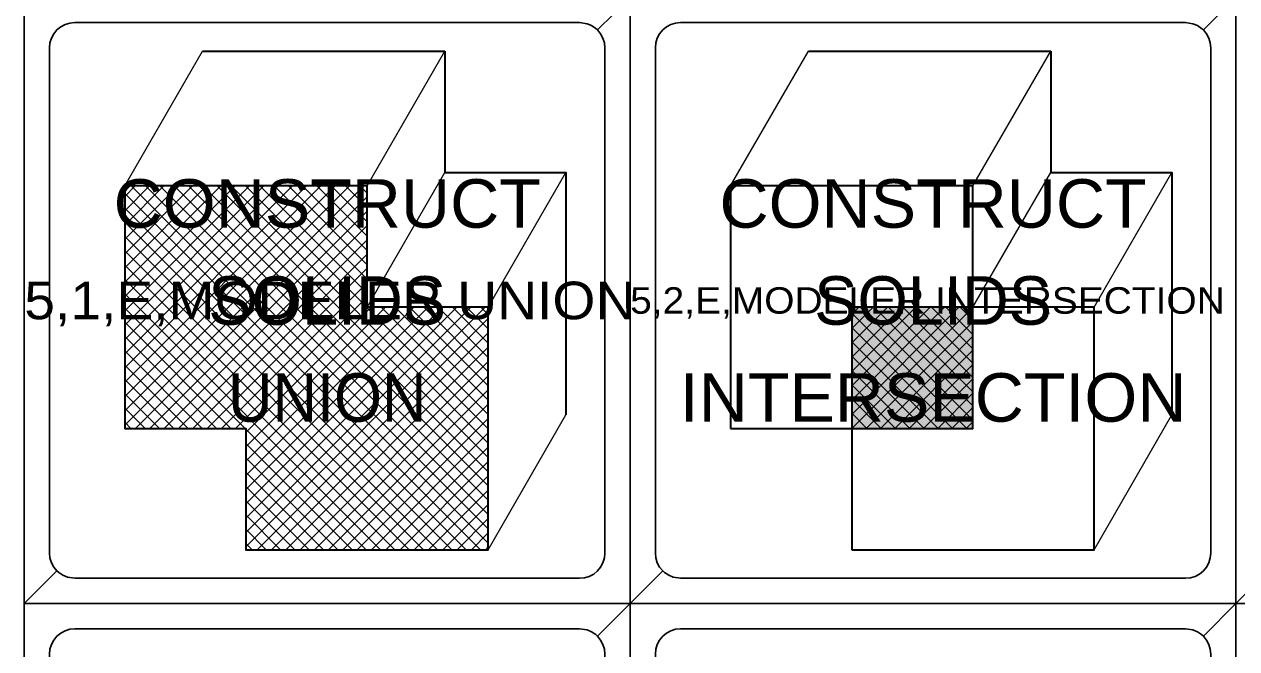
# Model space of a CAD drawing. Extents: x 95909.2 to 95923.3, y 90965 to 90971.2.
# Drawn here: x 95909.787 to 95910.988, y 90968.116 to 90968.734 of the extents above; entities that cross this region are included whole.
import ezdxf
from ezdxf.enums import TextEntityAlignment as Align

# ---------------------------------------------------------------- set-up
doc = ezdxf.new("R2010")
doc.units = 0
doc.header["$LTSCALE"] = 0.019
for name, color, linetype, lineweight in [('1', 7, 'Continuous', 25), ('10', 7, 'Continuous', 13), ('2', 7, 'Continuous', 25), ('3', 7, 'Continuous', 25), ('4', 7, 'Continuous', 25), ('6', 7, 'Continuous', 13)]:
    doc.layers.add(name, color=color, linetype=linetype, lineweight=lineweight)
doc.layers.add('5', color=7, linetype='Continuous')
doc.layers.add('63', color=7, linetype='Continuous')

msp = doc.modelspace()

# ---------------------------------------------------------------- hatches: boundary and pattern name
at = {"layer": '6'}
msp.add_hatch(color=256, dxfattribs=at).paths.add_polyline_path([(95910.6063, 90968.3336), (95910.7263, 90968.3336), (95910.7263, 90968.4536), (95910.6063, 90968.4536)])

# ---------------------------------------------------------------- linework, layer by layer
at = {"layer": '1'}
for points in [[(95909.7868, 90968.1603), (95910.3868, 90968.1603), (95910.3868, 90968.7603), (95909.7868, 90968.7603)], [(95910.3868, 90968.1603), (95910.9868, 90968.1603), (95910.9868, 90968.7603), (95910.3868, 90968.7603)], [(95910.9868, 90968.1603), (95911.5868, 90968.1603), (95911.5868, 90968.7603), (95910.9868, 90968.7603)], [(95909.7868, 90967.5603), (95910.3868, 90967.5603), (95910.3868, 90968.1603), (95909.7868, 90968.1603)], [(95910.3868, 90967.5603), (95910.9868, 90967.5603), (95910.9868, 90968.1603), (95910.3868, 90968.1603)], [(95910.9868, 90967.5603), (95911.5868, 90967.5603), (95911.5868, 90968.1603), (95910.9868, 90968.1603)]]:
    msp.add_lwpolyline(points, close=True, dxfattribs=at)
at = {"layer": '10'}
msp.add_lwpolyline([(95909.7868, 90971.1603), (95915.7868, 90971.1603), (95915.7868, 90966.3603), (95909.7868, 90966.3603)], close=True, dxfattribs=at)
at = {"layer": '2'}
for points in [[(95909.7868, 90968.1603), (95910.3868, 90968.1603), (95910.3868, 90968.7603), (95909.7868, 90968.7603)], [(95910.3868, 90968.1603), (95910.9868, 90968.1603), (95910.9868, 90968.7603), (95910.3868, 90968.7603)], [(95910.9868, 90968.1603), (95911.5868, 90968.1603), (95911.5868, 90968.7603), (95910.9868, 90968.7603)], [(95909.7868, 90967.5603), (95910.3868, 90967.5603), (95910.3868, 90968.1603), (95909.7868, 90968.1603)], [(95910.3868, 90967.5603), (95910.9868, 90967.5603), (95910.9868, 90968.1603), (95910.3868, 90968.1603)], [(95910.9868, 90967.5603), (95911.5868, 90967.5603), (95911.5868, 90968.1603), (95910.9868, 90968.1603)]]:
    msp.add_lwpolyline(points, close=True, dxfattribs=at)
at = {"layer": '3'}
for points in [[(95910.3868, 90968.7603), (95909.7868, 90968.7603), (95909.7868, 90968.1603), (95909.8191, 90968.1926), (95909.816, 90968.1964), (95909.8137, 90968.2007), (95909.8123, 90968.2054), (95909.8118, 90968.2103), (95909.8118, 90968.7103), (95909.8123, 90968.7152), (95909.8137, 90968.7199), (95909.816, 90968.7242), (95909.8191, 90968.728), (95909.8191, 90968.728), (95909.8229, 90968.7311), (95909.8272, 90968.7334), (95909.8319, 90968.7348), (95909.8368, 90968.7353), (95910.3368, 90968.7353), (95910.3441, 90968.7342), (95910.3486, 90968.7323), (95910.3527, 90968.7296), (95910.3545, 90968.728)], [(95910.9868, 90968.7603), (95910.3868, 90968.7603), (95910.3868, 90968.1603), (95910.4191, 90968.1926), (95910.416, 90968.1964), (95910.4137, 90968.2007), (95910.4123, 90968.2054), (95910.4118, 90968.2103), (95910.4118, 90968.7103), (95910.4123, 90968.7152), (95910.4137, 90968.7199), (95910.416, 90968.7242), (95910.4191, 90968.728), (95910.4191, 90968.728), (95910.4229, 90968.7311), (95910.4272, 90968.7334), (95910.4319, 90968.7348), (95910.4368, 90968.7353), (95910.9368, 90968.7353), (95910.9441, 90968.7342), (95910.9486, 90968.7323), (95910.9527, 90968.7296), (95910.9545, 90968.728)], [(95911.5868, 90968.7603), (95910.9868, 90968.7603), (95910.9868, 90968.1603), (95911.0191, 90968.1926), (95911.016, 90968.1964), (95911.0137, 90968.2007), (95911.0123, 90968.2054), (95911.0118, 90968.2103), (95911.0118, 90968.7103), (95911.0123, 90968.7152), (95911.0137, 90968.7199), (95911.016, 90968.7242), (95911.0191, 90968.728), (95911.0191, 90968.728), (95911.0229, 90968.7311), (95911.0272, 90968.7334), (95911.0319, 90968.7348), (95911.0368, 90968.7353), (95911.5368, 90968.7353), (95911.5441, 90968.7342), (95911.5486, 90968.7323), (95911.5527, 90968.7296), (95911.5545, 90968.728)], [(95910.3868, 90968.1603), (95909.7868, 90968.1603), (95909.7868, 90967.5603), (95909.8191, 90967.5926), (95909.816, 90967.5964), (95909.8137, 90967.6007), (95909.8123, 90967.6054), (95909.8118, 90967.6103), (95909.8118, 90968.1103), (95909.8123, 90968.1152), (95909.8137, 90968.1199), (95909.816, 90968.1242), (95909.8191, 90968.128), (95909.8191, 90968.128), (95909.8229, 90968.1311), (95909.8272, 90968.1334), (95909.8319, 90968.1348), (95909.8368, 90968.1353), (95910.3368, 90968.1353), (95910.3441, 90968.1342), (95910.3486, 90968.1323), (95910.3527, 90968.1296), (95910.3545, 90968.128)], [(95910.9868, 90968.1603), (95910.3868, 90968.1603), (95910.3868, 90967.5603), (95910.4191, 90967.5926), (95910.416, 90967.5964), (95910.4137, 90967.6007), (95910.4123, 90967.6054), (95910.4118, 90967.6103), (95910.4118, 90968.1103), (95910.4123, 90968.1152), (95910.4137, 90968.1199), (95910.416, 90968.1242), (95910.4191, 90968.128), (95910.4191, 90968.128), (95910.4229, 90968.1311), (95910.4272, 90968.1334), (95910.4319, 90968.1348), (95910.4368, 90968.1353), (95910.9368, 90968.1353), (95910.9441, 90968.1342), (95910.9486, 90968.1323), (95910.9527, 90968.1296), (95910.9545, 90968.128)], [(95911.5868, 90968.1603), (95910.9868, 90968.1603), (95910.9868, 90967.5603), (95911.0191, 90967.5926), (95911.016, 90967.5964), (95911.0137, 90967.6007), (95911.0123, 90967.6054), (95911.0118, 90967.6103), (95911.0118, 90968.1103), (95911.0123, 90968.1152), (95911.0137, 90968.1199), (95911.016, 90968.1242), (95911.0191, 90968.128), (95911.0191, 90968.128), (95911.0229, 90968.1311), (95911.0272, 90968.1334), (95911.0319, 90968.1348), (95911.0368, 90968.1353), (95911.5368, 90968.1353), (95911.5441, 90968.1342), (95911.5486, 90968.1323), (95911.5527, 90968.1296), (95911.5545, 90968.128)]]:
    msp.add_lwpolyline(points, close=True, dxfattribs=at)
at = {"layer": '4'}
for points in [[(95909.7868, 90968.1603), (95910.3868, 90968.1603), (95910.3868, 90968.7603), (95910.3545, 90968.728), (95910.3576, 90968.7242), (95910.3599, 90968.7199), (95910.3613, 90968.7152), (95910.3618, 90968.7103), (95910.3618, 90968.2103), (95910.3613, 90968.2054), (95910.3599, 90968.2007), (95910.3576, 90968.1964), (95910.3545, 90968.1926), (95910.3545, 90968.1926), (95910.3507, 90968.1895), (95910.3464, 90968.1872), (95910.3417, 90968.1858), (95910.3368, 90968.1853), (95909.8368, 90968.1853), (95909.8295, 90968.1864), (95909.825, 90968.1883), (95909.8209, 90968.191), (95909.8191, 90968.1926)], [(95910.3868, 90968.1603), (95910.9868, 90968.1603), (95910.9868, 90968.7603), (95910.9545, 90968.728), (95910.9576, 90968.7242), (95910.9599, 90968.7199), (95910.9613, 90968.7152), (95910.9618, 90968.7103), (95910.9618, 90968.2103), (95910.9613, 90968.2054), (95910.9599, 90968.2007), (95910.9576, 90968.1964), (95910.9545, 90968.1926), (95910.9545, 90968.1926), (95910.9507, 90968.1895), (95910.9464, 90968.1872), (95910.9417, 90968.1858), (95910.9368, 90968.1853), (95910.4368, 90968.1853), (95910.4295, 90968.1864), (95910.425, 90968.1883), (95910.4209, 90968.191), (95910.4191, 90968.1926)], [(95910.9868, 90968.1603), (95911.5868, 90968.1603), (95911.5868, 90968.7603), (95911.5545, 90968.728), (95911.5576, 90968.7242), (95911.5599, 90968.7199), (95911.5613, 90968.7152), (95911.5618, 90968.7103), (95911.5618, 90968.2103), (95911.5613, 90968.2054), (95911.5599, 90968.2007), (95911.5576, 90968.1964), (95911.5545, 90968.1926), (95911.5545, 90968.1926), (95911.5507, 90968.1895), (95911.5464, 90968.1872), (95911.5417, 90968.1858), (95911.5368, 90968.1853), (95911.0368, 90968.1853), (95911.0295, 90968.1864), (95911.025, 90968.1883), (95911.0209, 90968.191), (95911.0191, 90968.1926)], [(95909.7868, 90967.5603), (95910.3868, 90967.5603), (95910.3868, 90968.1603), (95910.3545, 90968.128), (95910.3576, 90968.1242), (95910.3599, 90968.1199), (95910.3613, 90968.1152), (95910.3618, 90968.1103), (95910.3618, 90967.6103), (95910.3613, 90967.6054), (95910.3599, 90967.6007), (95910.3576, 90967.5964), (95910.3545, 90967.5926), (95910.3545, 90967.5926), (95910.3507, 90967.5895), (95910.3464, 90967.5872), (95910.3417, 90967.5858), (95910.3368, 90967.5853), (95909.8368, 90967.5853), (95909.8295, 90967.5864), (95909.825, 90967.5883), (95909.8209, 90967.591), (95909.8191, 90967.5926)], [(95910.3868, 90967.5603), (95910.9868, 90967.5603), (95910.9868, 90968.1603), (95910.9545, 90968.128), (95910.9576, 90968.1242), (95910.9599, 90968.1199), (95910.9613, 90968.1152), (95910.9618, 90968.1103), (95910.9618, 90967.6103), (95910.9613, 90967.6054), (95910.9599, 90967.6007), (95910.9576, 90967.5964), (95910.9545, 90967.5926), (95910.9545, 90967.5926), (95910.9507, 90967.5895), (95910.9464, 90967.5872), (95910.9417, 90967.5858), (95910.9368, 90967.5853), (95910.4368, 90967.5853), (95910.4295, 90967.5864), (95910.425, 90967.5883), (95910.4209, 90967.591), (95910.4191, 90967.5926)]]:
    msp.add_lwpolyline(points, close=True, dxfattribs=at)
at = {"layer": '6'}
for p, q in [((95909.8863, 90968.5736), (95909.9633, 90968.707)), ((95910.1263, 90968.5736), (95910.2033, 90968.707)), ((95910.4863, 90968.5736), (95910.5633, 90968.707)), ((95910.7263, 90968.5736), (95910.8033, 90968.707)), ((95910.1263, 90968.4536), (95910.2033, 90968.587)), ((95910.2463, 90968.4536), (95910.3233, 90968.587)), ((95910.7263, 90968.4536), (95910.8033, 90968.587)), ((95910.8463, 90968.4536), (95910.9233, 90968.587)), ((95909.8863, 90968.5632), (95909.8967, 90968.5736)), ((95909.8863, 90968.5491), (95909.9108, 90968.5736)), ((95909.8863, 90968.5349), (95909.925, 90968.5736)), ((95909.8863, 90968.5208), (95909.9391, 90968.5736)), ((95909.8863, 90968.5066), (95909.9533, 90968.5736)), ((95909.8863, 90968.4925), (95909.9674, 90968.5736)), ((95909.8863, 90968.4783), (95909.9816, 90968.5736)), ((95909.8863, 90968.4642), (95909.9957, 90968.5736)), ((95909.8863, 90968.4501), (95910.0098, 90968.5736)), ((95909.8863, 90968.4359), (95910.024, 90968.5736)), ((95909.8863, 90968.4218), (95910.0381, 90968.5736)), ((95909.8863, 90968.4076), (95910.0523, 90968.5736)), ((95909.8863, 90968.3935), (95910.0664, 90968.5736)), ((95909.8863, 90968.3794), (95910.0805, 90968.5736)), ((95909.8863, 90968.3652), (95910.0947, 90968.5736)), ((95909.8863, 90968.3511), (95910.1088, 90968.5736)), ((95909.8863, 90968.3369), (95910.123, 90968.5736)), ((95909.8863, 90968.566), (95910.2387, 90968.2136)), ((95909.8928, 90968.5736), (95910.2463, 90968.2201)), ((95909.8971, 90968.3336), (95910.1263, 90968.5628)), ((95909.907, 90968.5736), (95910.2463, 90968.2343)), ((95909.9211, 90968.5736), (95910.2463, 90968.2484)), ((95909.9352, 90968.5736), (95910.2463, 90968.2625)), ((95909.9494, 90968.5736), (95910.2463, 90968.2767)), ((95909.9635, 90968.5736), (95910.2463, 90968.2908)), ((95909.9777, 90968.5736), (95910.2463, 90968.305)), ((95909.9918, 90968.5736), (95910.2463, 90968.3191)), ((95910.0059, 90968.5736), (95910.2463, 90968.3332)), ((95910.0201, 90968.5736), (95910.1263, 90968.4674)), ((95910.0342, 90968.5736), (95910.1263, 90968.4815)), ((95910.0484, 90968.5736), (95910.1263, 90968.4957)), ((95910.0625, 90968.5736), (95910.1263, 90968.5098)), ((95910.0767, 90968.5736), (95910.1263, 90968.524)), ((95910.0908, 90968.5736), (95910.1263, 90968.5381)), ((95910.1049, 90968.5736), (95910.1263, 90968.5522)), ((95910.1191, 90968.5736), (95910.1263, 90968.5664)), ((95909.8863, 90968.5518), (95910.2245, 90968.2136)), ((95909.9113, 90968.3336), (95910.1263, 90968.5486)), ((95909.8863, 90968.5377), (95910.2104, 90968.2136)), ((95909.9254, 90968.3336), (95910.1263, 90968.5345)), ((95909.8863, 90968.5235), (95910.1962, 90968.2136)), ((95909.9395, 90968.3336), (95910.1263, 90968.5204)), ((95909.8863, 90968.5094), (95910.1821, 90968.2136)), ((95909.9537, 90968.3336), (95910.1263, 90968.5062)), ((95909.8863, 90968.4953), (95910.168, 90968.2136)), ((95909.9678, 90968.3336), (95910.1263, 90968.4921)), ((95909.8863, 90968.4811), (95910.1538, 90968.2136)), ((95909.8863, 90968.467), (95910.1397, 90968.2136)), ((95909.982, 90968.3336), (95910.1263, 90968.4779)), ((95909.9961, 90968.3336), (95910.1263, 90968.4638)), ((95909.8863, 90968.4528), (95910.0055, 90968.3336)), ((95910.0063, 90968.3296), (95910.1303, 90968.4536)), ((95910.0063, 90968.3155), (95910.1444, 90968.4536)), ((95910.0063, 90968.3014), (95910.1585, 90968.4536)), ((95910.0063, 90968.2872), (95910.1727, 90968.4536)), ((95910.0063, 90968.2731), (95910.1868, 90968.4536)), ((95910.0063, 90968.2589), (95910.201, 90968.4536)), ((95910.0063, 90968.2448), (95910.2151, 90968.4536)), ((95910.0063, 90968.2307), (95910.2292, 90968.4536)), ((95910.0063, 90968.2165), (95910.2434, 90968.4536)), ((95910.0175, 90968.2136), (95910.2463, 90968.4424)), ((95910.1401, 90968.4536), (95910.2463, 90968.3474)), ((95910.1542, 90968.4536), (95910.2463, 90968.3615)), ((95910.1684, 90968.4536), (95910.2463, 90968.3757)), ((95910.1825, 90968.4536), (95910.2463, 90968.3898)), ((95910.1967, 90968.4536), (95910.2463, 90968.404)), ((95910.2108, 90968.4536), (95910.2463, 90968.4181)), ((95910.2249, 90968.4536), (95910.2463, 90968.4322)), ((95910.2391, 90968.4536), (95910.2463, 90968.4464)), ((95910.6063, 90968.4465), (95910.6134, 90968.4536)), ((95910.6063, 90968.4324), (95910.6275, 90968.4536)), ((95910.6063, 90968.4183), (95910.6416, 90968.4536)), ((95910.6063, 90968.4041), (95910.6558, 90968.4536)), ((95910.6063, 90968.39), (95910.6699, 90968.4536)), ((95910.6063, 90968.3758), (95910.6841, 90968.4536)), ((95910.6063, 90968.3617), (95910.6982, 90968.4536)), ((95910.6063, 90968.3475), (95910.7124, 90968.4536)), ((95910.6063, 90968.4476), (95910.7203, 90968.3336)), ((95910.6065, 90968.3336), (95910.7263, 90968.4534)), ((95910.6145, 90968.4536), (95910.7263, 90968.3418)), ((95910.6286, 90968.4536), (95910.7263, 90968.3559)), ((95910.6427, 90968.4536), (95910.7263, 90968.37)), ((95910.6569, 90968.4536), (95910.7263, 90968.3842)), ((95910.671, 90968.4536), (95910.7263, 90968.3983)), ((95910.6852, 90968.4536), (95910.7263, 90968.4125)), ((95910.6993, 90968.4536), (95910.7263, 90968.4266)), ((95910.7135, 90968.4536), (95910.7263, 90968.4408)), ((95909.8863, 90968.4387), (95909.9914, 90968.3336)), ((95910.6063, 90968.4335), (95910.7062, 90968.3336)), ((95910.6206, 90968.3336), (95910.7263, 90968.4393)), ((95909.8863, 90968.4245), (95909.9772, 90968.3336)), ((95910.0317, 90968.2136), (95910.2463, 90968.4282)), ((95910.6063, 90968.4193), (95910.692, 90968.3336)), ((95910.6348, 90968.3336), (95910.7263, 90968.4251)), ((95909.8863, 90968.4104), (95909.9631, 90968.3336)), ((95910.0458, 90968.2136), (95910.2463, 90968.4141)), ((95910.6489, 90968.3336), (95910.7263, 90968.411)), ((95909.8863, 90968.3963), (95909.949, 90968.3336)), ((95910.06, 90968.2136), (95910.2463, 90968.3999)), ((95910.6063, 90968.4052), (95910.6779, 90968.3336)), ((95910.6631, 90968.3336), (95910.7263, 90968.3968)), ((95909.8863, 90968.3821), (95909.9348, 90968.3336)), ((95910.0741, 90968.2136), (95910.2463, 90968.3858)), ((95910.6063, 90968.391), (95910.6637, 90968.3336)), ((95910.6772, 90968.3336), (95910.7263, 90968.3827)), ((95910.0882, 90968.2136), (95910.2463, 90968.3717)), ((95910.6063, 90968.3769), (95910.6496, 90968.3336)), ((95909.8863, 90968.368), (95909.9207, 90968.3336)), ((95910.6063, 90968.3628), (95910.6355, 90968.3336)), ((95910.6914, 90968.3336), (95910.7263, 90968.3685)), ((95909.8863, 90968.3538), (95909.9065, 90968.3336)), ((95910.1024, 90968.2136), (95910.2463, 90968.3575)), ((95910.2463, 90968.2136), (95910.3233, 90968.347)), ((95910.6063, 90968.3486), (95910.6213, 90968.3336)), ((95910.7055, 90968.3336), (95910.7263, 90968.3544)), ((95910.8463, 90968.2136), (95910.9233, 90968.347)), ((95909.8863, 90968.3397), (95909.8924, 90968.3336)), ((95910.1165, 90968.2136), (95910.2463, 90968.3434)), ((95910.6063, 90968.3345), (95910.6072, 90968.3336)), ((95910.7196, 90968.3336), (95910.7263, 90968.3403)), ((95910.0063, 90968.3328), (95910.1255, 90968.2136)), ((95910.1307, 90968.2136), (95910.2463, 90968.3292)), ((95910.0063, 90968.3187), (95910.1114, 90968.2136)), ((95910.1448, 90968.2136), (95910.2463, 90968.3151)), ((95910.0063, 90968.3045), (95910.0972, 90968.2136)), ((95910.159, 90968.2136), (95910.2463, 90968.3009)), ((95910.0063, 90968.2904), (95910.0831, 90968.2136)), ((95910.1731, 90968.2136), (95910.2463, 90968.2868)), ((95910.0063, 90968.2763), (95910.069, 90968.2136)), ((95910.0063, 90968.2621), (95910.0548, 90968.2136)), ((95910.1872, 90968.2136), (95910.2463, 90968.2727)), ((95910.2014, 90968.2136), (95910.2463, 90968.2585)), ((95910.0063, 90968.248), (95910.0407, 90968.2136)), ((95910.2155, 90968.2136), (95910.2463, 90968.2444)), ((95910.0063, 90968.2338), (95910.0265, 90968.2136)), ((95910.2297, 90968.2136), (95910.2463, 90968.2302)), ((95910.0063, 90968.2197), (95910.0124, 90968.2136)), ((95910.2438, 90968.2136), (95910.2463, 90968.2161))]:
    msp.add_line(p, q, dxfattribs=at)
at = {"layer": '6', "lineweight": 35}
for p, q in [((95909.9633, 90968.707), (95910.2033, 90968.707)), ((95910.5633, 90968.707), (95910.8033, 90968.707))]:
    msp.add_line(p, q, dxfattribs=at)
for points in [[(95910.2033, 90968.707), (95910.2033, 90968.587), (95910.3233, 90968.587), (95910.3233, 90968.347)], [(95910.8033, 90968.707), (95910.8033, 90968.587), (95910.9233, 90968.587), (95910.9233, 90968.347)]]:
    msp.add_lwpolyline(points, dxfattribs=at)
for points in [[(95909.8863, 90968.5736), (95909.8863, 90968.3336), (95910.0063, 90968.3336), (95910.0063, 90968.2136), (95910.2463, 90968.2136), (95910.2463, 90968.4536), (95910.1263, 90968.4536), (95910.1263, 90968.5736)], [(95910.4863, 90968.3336), (95910.7263, 90968.3336), (95910.7263, 90968.5736), (95910.4863, 90968.5736)], [(95910.6063, 90968.2136), (95910.8463, 90968.2136), (95910.8463, 90968.4536), (95910.6063, 90968.4536)], [(95910.6063, 90968.3336), (95910.7263, 90968.3336), (95910.7263, 90968.4536), (95910.6063, 90968.4536)]]:
    msp.add_lwpolyline(points, close=True, dxfattribs=at)

# ---------------------------------------------------------------- texts
at = {"layer": '5'}
for s, width, p in [('CONSTRUCT', 1.05, (95910.0868, 90968.5323)), ('CONSTRUCT', 1.05, (95910.6868, 90968.5323)), ('UNION', 0.95, (95910.08685, 90968.3403)), ('INTERSECTION', 1.05, (95910.68685, 90968.3403))]:
    msp.add_text(s, height=0.048, dxfattribs=dict(at, width=width)).set_placement(p, align=Align.CENTER)
for p in [(95910.0868, 90968.4363), (95910.6868, 90968.4363)]:
    msp.add_text('SOLIDS', height=0.048, dxfattribs=at).set_placement(p, align=Align.CENTER)
at = {"layer": '63', "width": 1.1}
for s, height, p in [('5,1,E,MODELER UNION', 0.0372, (95909.7868, 90968.4417)), ('5,2,E,MODELER INTERSECTION', 0.0262, (95910.3868, 90968.4472))]:
    msp.add_text(s, height=height, dxfattribs=at).set_placement(p)

doc.saveas('drawing.dxf')
